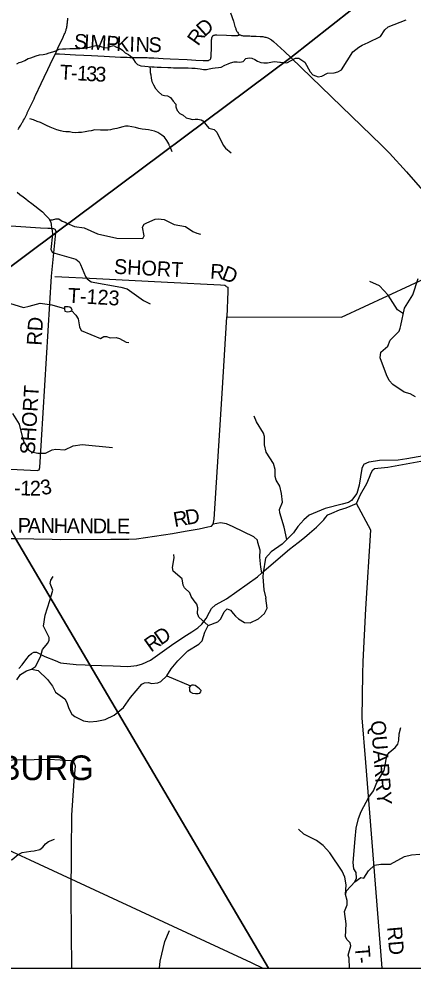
# Model space of a CAD drawing. Extents: x 0 to 1052, y -194 to 246.
# Drawn here: x 4.134 to 5.648, y 14.205 to 17.846 of the extents above; entities that cross this region are included whole.
import ezdxf

# ---------------------------------------------------------------- set-up
doc = ezdxf.new("R2010")
doc.units = 0
for name, color, linetype in [('GM_X_Corporation', 7, 'Continuous'), ('GM_X_Corporation_Text', 7, 'Continuous'), ('GM_X_County_Road', 7, 'Continuous'), ('GM_X_County_Road_Text', 7, 'Continuous'), ('GM_X_Minor_Lake', 7, 'Continuous'), ('GM_X_Minor_River', 7, 'Continuous'), ('GM_X_Rail_Line', 7, 'Continuous'), ('GM_X_State_Route', 7, 'Continuous'), ('GM_X_Township_Road', 7, 'Continuous'), ('GM_X_Township_Road_Text', 7, 'Continuous')]:
    doc.layers.add(name, color=color, linetype=linetype)

msp = doc.modelspace()

# ---------------------------------------------------------------- linework, layer by layer
at = {"layer": 'GM_X_Corporation'}
for points in [[(5.491, 17.9457), (5.1788, 17.6981), (4.2749, 17.0262), (3.6964, 16.595), (3.6869, 16.5875), (3.6921, 16.5787), (4.0068, 16.0455), (4.1203, 15.8533), (4.4065, 15.3682), (5.0927, 14.2055), (8.7822, 14.2055), (8.7822, 19.8853)], [(5.491, 17.9457), (5.1788, 17.6981), (4.2749, 17.0262), (3.6964, 16.595)], [(3.6964, 16.595), (4.2749, 17.0262), (5.1788, 17.6981), (5.491, 17.9457)], [(3.6964, 16.595), (4.2749, 17.0262), (5.1788, 17.6981), (5.491, 17.9457)], [(2.3779, 14.2055), (5.0927, 14.2055), (4.4065, 15.3682), (4.1203, 15.8533)], [(2.3779, 14.2055), (8.7822, 14.2055)]]:
    msp.add_lwpolyline(points, dxfattribs=at)
at = {"layer": 'GM_X_County_Road'}
for points in [[(3.8855, 17.0657), (3.8945, 17.0651), (3.9379, 17.0625), (4.0353, 17.0565), (4.0912, 17.053), (4.1216, 17.0513), (4.2171, 17.0454), (4.245, 17.0437), (4.2555, 17.0431), (4.2636, 17.0425), (4.2655, 17.0423), (4.2672, 17.0418), (4.2696, 17.0409), (4.2711, 17.04), (4.2725, 17.0387), (4.2735, 17.0372), (4.274, 17.0361), (4.2745, 17.0349), (4.2748, 17.0338), (4.2751, 17.0325), (4.2753, 17.0297), (4.2751, 17.0257)], [(4.2609, 15.8504), (4.2924, 15.8499), (4.4871, 15.8502), (4.5558, 15.8503), (4.5854, 15.8513), (4.7233, 15.8727), (4.7727, 15.8812), (4.8266, 15.8908), (4.86, 15.8975), (4.8741, 15.9005), (4.8794, 15.9077), (4.8841, 15.9278), (4.9141, 16.4089), (4.9327, 16.7033), (5.3736, 16.7026), (5.7266, 16.866), (5.9068, 16.9578)], [(4.4956, 15.3646), (4.5516, 15.3626), (4.5869, 15.3659), (4.609, 15.3717), (4.6386, 15.3858), (4.7289, 15.4498), (4.777, 15.4824), (4.7974, 15.4957), (4.8207, 15.5106), (4.8361, 15.5245), (4.8533, 15.546), (4.8654, 15.5704), (4.8737, 15.5842), (4.8892, 15.5986), (4.9058, 15.6074), (4.9312, 15.6218), (5.0502, 15.7058), (5.0667, 15.7219), (5.1733, 15.8119), (5.2071, 15.838), (5.2304, 15.8576), (5.2502, 15.8731), (5.2765, 15.8969), (5.3047, 15.9244), (5.3111, 15.9343), (5.3199, 15.9433), (5.3355, 15.9497), (5.3659, 15.9629), (5.3914, 15.9711), (5.4302, 15.988), (5.4458, 16.0213), (5.4701, 16.0647), (5.4802, 16.0883), (5.4871, 16.1045), (5.4931, 16.1165), (5.5, 16.1216), (5.5514, 16.1267), (5.6776, 16.1495)], [(3.4438, 15.9251), (3.5208, 15.8958), (3.6683, 15.8481), (3.7274, 15.8293), (3.7384, 15.8266), (4.0062, 15.8493), (4.054, 15.8506), (4.1026, 15.853), (4.1205, 15.8527), (4.2609, 15.8504)], [(4.1336, 15.3538), (4.1462, 15.3686), (4.1565, 15.3822), (4.1652, 15.3946), (4.1734, 15.4044), (4.182, 15.4126), (4.1911, 15.4172), (4.2013, 15.4167), (4.2328, 15.4004), (4.2726, 15.3848), (4.2931, 15.3762), (4.3533, 15.37), (4.3877, 15.3684), (4.4067, 15.3677), (4.4956, 15.3646)]]:
    msp.add_lwpolyline(points, dxfattribs=at)
at = {"layer": 'GM_X_Minor_Lake'}
for points in [[(4.3089, 16.7334), (4.3095, 16.7246), (4.3201, 16.7222), (4.3281, 16.7237), (4.3327, 16.7247), (4.3381, 16.7296), (4.3359, 16.7357), (4.3287, 16.7403), (4.3227, 16.7423), (4.3166, 16.7424), (4.3123, 16.7424)], [(4.3123, 16.7424), (4.3093, 16.7421), (4.3089, 16.7334)], [(4.7984, 15.2901), (4.7934, 15.2875), (4.788, 15.2819), (4.7888, 15.276), (4.7892, 15.2683), (4.7918, 15.2648), (4.8008, 15.2601), (4.8118, 15.2583), (4.8224, 15.2589), (4.8289, 15.2603), (4.8332, 15.2651), (4.8336, 15.2697), (4.8269, 15.2763), (4.821, 15.2817), (4.8161, 15.2856), (4.8105, 15.2887), (4.8044, 15.29)], [(4.8044, 15.29), (4.7984, 15.2901)]]:
    msp.add_lwpolyline(points, dxfattribs=at)
at = {"layer": 'GM_X_Minor_River'}
for points in [[(5.4749, 17.7558), (5.5233, 17.7791), (5.54, 17.805), (5.5523, 17.8162), (5.6217, 17.8428)], [(4.1254, 17.6736), (4.135, 17.6787), (4.1449, 17.682), (4.1567, 17.6868), (4.1697, 17.6939), (4.1793, 17.6968), (4.1896, 17.7008), (4.1999, 17.7045), (4.2132, 17.7089), (4.2265, 17.7102), (4.2402, 17.7123), (4.2505, 17.716), (4.2643, 17.7203), (4.275, 17.7244), (4.2887, 17.7299), (4.3009, 17.7316), (4.3142, 17.7318), (4.3298, 17.7324), (4.3419, 17.733), (4.3575, 17.7328), (4.3681, 17.733), (4.3845, 17.734), (4.4043, 17.7383), (4.4188, 17.7423), (4.4291, 17.7444), (4.4393, 17.7435), (4.4518, 17.7392), (4.4643, 17.7364), (4.4742, 17.7358), (4.4845, 17.7399), (4.4967, 17.7439), (4.5091, 17.7377), (4.5193, 17.7356), (4.5318, 17.7264), (4.5419, 17.7167), (4.5547, 17.7101), (4.5671, 17.7001), (4.5738, 17.6905), (4.5798, 17.6809), (4.5891, 17.671), (4.6027, 17.6658), (4.6171, 17.6645), (4.6297, 17.664), (4.6437, 17.6627), (4.6536, 17.6621), (4.6646, 17.6616), (4.6798, 17.6607), (4.706, 17.6603), (4.7174, 17.6594), (4.7272, 17.6589), (4.7379, 17.6584), (4.7492, 17.6583), (4.7606, 17.6589), (4.772, 17.6591), (4.7838, 17.6586), (4.7982, 17.658), (4.8108, 17.6575), (4.8202, 17.6562), (4.8297, 17.6546), (4.8426, 17.6521), (4.8548, 17.6519), (4.8643, 17.6549), (4.8776, 17.6577), (4.8875, 17.6591), (4.9004, 17.6601), (4.9107, 17.6615), (4.9249, 17.6685), (4.9371, 17.6744), (4.947, 17.6777), (4.9604, 17.6813), (4.9718, 17.6819), (4.982, 17.6803), (4.9957, 17.6824), (5.0054, 17.6948), (5.0187, 17.6969), (5.0282, 17.6953), (5.0406, 17.6909), (5.0504, 17.684), (5.0633, 17.6789), (5.0743, 17.6776), (5.0883, 17.6778), (5.1142, 17.6828), (5.1264, 17.6818)], [(5.1386, 17.6799), (5.1635, 17.6784), (5.1964, 17.6955), (5.2085, 17.6957), (5.2319, 17.6799), (5.2522, 17.6428), (5.2627, 17.6324), (5.2839, 17.6246), (5.2968, 17.6271), (5.3186, 17.6386), (5.3448, 17.6398), (5.3585, 17.6431), (5.3734, 17.6512), (5.4167, 17.7194), (5.439, 17.7377), (5.4524, 17.7459), (5.4749, 17.7558)], [(4.6366, 17.6633), (4.6375, 17.6517), (4.6385, 17.6411), (4.6399, 17.6312), (4.6416, 17.6186), (4.6445, 17.6068), (4.6508, 17.5939), (4.6585, 17.5793), (4.6698, 17.5667), (4.6829, 17.5555), (4.6927, 17.5519), (4.7049, 17.5506), (4.7158, 17.5444), (4.7263, 17.531), (4.7371, 17.5187), (4.737, 17.5088), (4.7417, 17.4955), (4.7518, 17.4836), (4.7647, 17.4766), (4.7763, 17.4666), (4.7869, 17.4638), (4.8009, 17.4602), (4.8108, 17.4612), (4.8207, 17.4618), (4.8343, 17.4597), (4.8397, 17.4551)], [(5.1264, 17.6818), (5.1358, 17.6806), (5.1386, 17.6799)], [(4.712, 17.3591), (4.71, 17.3668), (4.7018, 17.3798), (4.6929, 17.3921), (4.6827, 17.3998), (4.668, 17.4106), (4.6552, 17.4154), (4.6431, 17.4186), (4.631, 17.4202), (4.6203, 17.4215), (4.6074, 17.4228), (4.5938, 17.426), (4.5821, 17.4296), (4.5681, 17.4328), (4.5533, 17.4349), (4.543, 17.4347), (4.5331, 17.4325), (4.5194, 17.4285), (4.5095, 17.426), (4.495, 17.4228), (4.4855, 17.4206), (4.4748, 17.4196), (4.4612, 17.419), (4.4471, 17.42), (4.4258, 17.4202), (4.4114, 17.4174), (4.4007, 17.4153), (4.3882, 17.4135), (4.3741, 17.4107), (4.3623, 17.4104), (4.3513, 17.4098), (4.3384, 17.4111), (4.3274, 17.4128), (4.3145, 17.4137), (4.3038, 17.4146), (4.2936, 17.4166), (4.2792, 17.4202), (4.2671, 17.4257), (4.2539, 17.4316), (4.2403, 17.4378), (4.2166, 17.4484), (4.2037, 17.4524), (4.1897, 17.4594), (4.1757, 17.4633)], [(4.8397, 17.4551), (4.8633, 17.4275), (4.8837, 17.4215), (4.8946, 17.4119), (4.9186, 17.3619), (4.9272, 17.3504), (4.9493, 17.3331)], [(4.712, 17.3591), (4.7214, 17.3381)], [(4.1275, 17.1811), (4.1373, 17.1727), (4.15, 17.1634), (4.1598, 17.1564), (4.1696, 17.148), (4.1831, 17.1387), (4.2237, 17.1063), (4.2376, 17.0928), (4.2488, 17.0805), (4.2566, 17.0671), (4.258, 17.0572), (4.259, 17.0451), (4.2615, 17.0336), (4.2623, 17.0211)], [(4.2518, 17.0753), (4.2628, 17.0758), (4.2758, 17.0794), (4.2872, 17.08), (4.2996, 17.0703), (4.3109, 17.0668), (4.3181, 17.0631)], [(4.3181, 17.0631), (4.3475, 17.0501), (4.3842, 17.0455), (4.4351, 17.0217), (4.5093, 17.0057), (4.6102, 17.0041), (4.6148, 17.0139), (4.6088, 17.0473), (4.615, 17.059), (4.625, 17.0638), (4.657, 17.0775), (4.6688, 17.0792), (4.6919, 17.0771), (4.7303, 17.058), (4.7743, 17.0503), (4.8021, 17.0309), (4.8172, 17.0243), (4.8315, 17.02)], [(4.2623, 17.0211), (4.2568, 16.9617), (4.2631, 16.9498), (4.3519, 16.9252), (4.3647, 16.9141), (4.3703, 16.9045), (4.3894, 16.8588), (4.3965, 16.8492), (4.4115, 16.8372), (4.5254, 16.8173), (4.5496, 16.8105), (4.6121, 16.7665), (4.6381, 16.7537)], [(3.9964, 16.8212), (4.032, 16.7986), (4.0579, 16.7759), (4.0812, 16.7612), (4.1515, 16.7398), (4.1736, 16.7441), (4.2151, 16.7561), (4.2602, 16.7495), (4.309, 16.7357)], [(5.6109, 16.7156), (5.5878, 16.7301), (5.5527, 16.7864), (5.5195, 16.8219), (5.4822, 16.8384)], [(5.6572, 16.3968), (5.6366, 16.4077), (5.6143, 16.4149), (5.5704, 16.4441), (5.5559, 16.4595), (5.546, 16.4808), (5.5212, 16.5461), (5.5238, 16.568), (5.5511, 16.5908), (5.5598, 16.6145), (5.5945, 16.6489), (5.5985, 16.6594), (5.6013, 16.6708), (5.6156, 16.7373), (5.6468, 16.7884), (5.6671, 16.851)], [(4.3363, 16.728), (4.3526, 16.7101), (4.3615, 16.6963), (4.3664, 16.6651), (4.3727, 16.6514), (4.4474, 16.6205), (4.4604, 16.6276), (4.4703, 16.6278), (4.4843, 16.6231), (4.5074, 16.6236), (4.5203, 16.6208), (4.5455, 16.6061), (4.5565, 16.6044)], [(4.1088, 16.3321), (4.1348, 16.2919), (4.1489, 16.2337), (4.1533, 16.2208), (4.1707, 16.1936), (4.1816, 16.1855), (4.2062, 16.1811), (4.2165, 16.1805), (4.2355, 16.1811), (4.261, 16.1929), (4.2755, 16.1958), (4.3104, 16.1935), (4.3417, 16.2083), (4.377, 16.2131), (4.4929, 16.2019)], [(5.1628, 15.8496), (5.1526, 15.8964), (5.1362, 15.9513), (5.1349, 15.9649), (5.1462, 15.9921), (5.1429, 16.0263), (5.136, 16.0533), (5.1226, 16.077), (5.1187, 16.0907), (5.1186, 16.1177), (5.1117, 16.1405), (5.0834, 16.1845), (5.0773, 16.2119), (5.0766, 16.2449), (5.0734, 16.2575), (5.0458, 16.301), (5.0374, 16.3228)], [(5.4588, 16.1386), (5.4796, 16.1474), (5.5184, 16.1536), (5.5908, 16.1551), (5.6239, 16.1603), (5.6893, 16.171)], [(5.4588, 16.1386), (5.4514, 16.1216), (5.4411, 16.058), (5.4323, 16.0262), (5.4119, 15.9984), (5.3993, 15.9913), (5.376, 15.9852), (5.3098, 15.9678), (5.2484, 15.9431), (5.2277, 15.9251), (5.205, 15.8988), (5.188, 15.8751), (5.1446, 15.8313), (5.1024, 15.8014), (5.0805, 15.7782), (5.0715, 15.7217), (5.0709, 15.7062), (5.0744, 15.6561), (5.082, 15.6237)], [(4.8066, 15.6144), (4.7956, 15.631), (4.7909, 15.6443), (4.7699, 15.6639), (4.7647, 15.6735), (4.7612, 15.6978), (4.7263, 15.7274), (4.7238, 15.7419), (4.7307, 15.7786), (4.7283, 15.7923)], [(4.2519, 15.6148), (4.2637, 15.6549), (4.2534, 15.6808), (4.2566, 15.6937), (4.2655, 15.7072)], [(4.1253, 15.311), (4.1401, 15.332), (4.1627, 15.3459), (4.1826, 15.3516), (4.2083, 15.3462), (4.2437, 15.3118), (4.2629, 15.2867), (4.2742, 15.2637), (4.3105, 15.2376), (4.3182, 15.2246), (4.3243, 15.2047), (4.3305, 15.1913), (4.3371, 15.1798), (4.3479, 15.1705), (4.3813, 15.1539), (4.4067, 15.15), (4.4329, 15.1522), (4.4645, 15.1591), (4.4994, 15.1759), (4.5349, 15.2045), (4.5622, 15.2438), (4.6053, 15.2946), (4.6168, 15.2997), (4.6309, 15.3009), (4.6425, 15.2973), (4.6673, 15.2998), (4.6795, 15.3049), (4.7015, 15.3261), (4.7184, 15.3527), (4.7437, 15.3841), (4.782, 15.4228), (4.8253, 15.4478), (4.8373, 15.4601), (4.8475, 15.4944), (4.8613, 15.5196), (4.8976, 15.5337), (4.9088, 15.5456), (4.9222, 15.5719), (4.9335, 15.5831), (4.9467, 15.5783), (4.9563, 15.5656), (4.9656, 15.5555), (4.9771, 15.5447), (5.0004, 15.531), (5.0227, 15.529), (5.0542, 15.5455), (5.0769, 15.5656), (5.0868, 15.5859), (5.082, 15.6237)], [(4.1826, 15.3516), (4.1972, 15.362), (4.2165, 15.3992), (4.2239, 15.4275), (4.2445, 15.4514), (4.2493, 15.4631), (4.2495, 15.4733), (4.2287, 15.5173), (4.2341, 15.5594), (4.2519, 15.6148)], [(4.8613, 15.5196), (4.8243, 15.5518), (4.8197, 15.5656), (4.8212, 15.5875), (4.8166, 15.6009), (4.8066, 15.6144)], [(4.7015, 15.3261), (4.7934, 15.2875)], [(5.4489, 14.806), (5.4785, 14.8607), (5.4959, 14.8847), (5.5092, 14.9176), (5.537, 14.9631), (5.5476, 15.0198), (5.5557, 15.0322), (5.5797, 15.0516), (5.5897, 15.064), (5.5937, 15.0795), (5.594, 15.1038), (5.6012, 15.1284)], [(3.8011, 14.9727), (3.8224, 14.9571), (3.8286, 14.9463), (3.8556, 14.8494), (3.8948, 14.8202), (3.9117, 14.7907), (3.9413, 14.7487), (3.9551, 14.7405), (3.9917, 14.7273), (4.0025, 14.7172), (4.0188, 14.6767), (4.0359, 14.6403), (4.0606, 14.6212), (4.0824, 14.6121), (4.1084, 14.6218), (4.1304, 14.6411), (4.1461, 14.648), (4.18, 14.6542), (4.1921, 14.6551), (4.2135, 14.66), (4.2258, 14.6685), (4.2359, 14.6816), (4.2478, 14.6908), (4.2704, 14.6995)], [(5.424, 14.5365), (5.431, 14.5497), (5.4299, 14.5717), (5.4207, 14.5859), (5.4173, 14.6099), (5.4258, 14.7016), (5.4292, 14.7414), (5.4382, 14.7796), (5.4489, 14.806)], [(5.3886, 14.4878), (5.3907, 14.5242), (5.3856, 14.5543), (5.3754, 14.5765), (5.3277, 14.6476), (5.3024, 14.6754), (5.2766, 14.6952), (5.2288, 14.7192), (5.2079, 14.7385)], [(5.447, 14.5521), (5.4582, 14.5499), (5.4764, 14.5781), (5.5001, 14.6006), (5.5244, 14.6044), (5.5607, 14.604), (5.6148, 14.6336), (5.6425, 14.6401), (5.6739, 14.6419)], [(5.3886, 14.4878), (5.3926, 14.501), (5.424, 14.5365), (5.447, 14.5521)], [(5.4032, 14.2055), (5.4028, 14.2431), (5.3984, 14.2546), (5.4082, 14.2908), (5.4061, 14.3015), (5.3942, 14.3131), (5.3887, 14.3257), (5.3903, 14.375), (5.3847, 14.4218), (5.3947, 14.4478), (5.3946, 14.4645), (5.3886, 14.4878)], [(4.6738, 14.2055), (4.6763, 14.2322), (4.694, 14.307), (4.7122, 14.3496)]]:
    msp.add_lwpolyline(points, dxfattribs=at)
at = {"layer": 'GM_X_Rail_Line'}
msp.add_lwpolyline([(3.0187, 15.1565), (3.1162, 15.1123), (3.6083, 14.8817), (4.1755, 14.6202), (5.0257, 14.2265), (5.0707, 14.2055)], dxfattribs=at)
at = {"layer": 'GM_X_State_Route'}
for points in [[(4.1306, 17.4222), (4.134, 17.4272), (4.1364, 17.431), (4.1388, 17.4348), (4.1413, 17.4389), (4.1441, 17.4438), (4.1468, 17.4486), (4.1487, 17.4521), (4.1516, 17.4576), (4.1547, 17.4634), (4.1648, 17.4835), (4.1658, 17.4856), (4.1681, 17.4905), (4.192, 17.5403), (4.1934, 17.5433), (4.1952, 17.5471), (4.1977, 17.5524), (4.2196, 17.599), (4.2311, 17.6231), (4.2446, 17.6518), (4.2633, 17.6903), (4.2737, 17.7127), (4.2837, 17.7343), (4.304, 17.7769), (4.3081, 17.7861), (4.3098, 17.7899), (4.3111, 17.7932), (4.3121, 17.7957), (4.313, 17.798), (4.3139, 17.8007), (4.3147, 17.8032), (4.3153, 17.805), (4.3158, 17.8068), (4.3166, 17.81), (4.3174, 17.8134), (4.3181, 17.8169), (4.3187, 17.8206), (4.3192, 17.8246), (4.3196, 17.8273), (4.32, 17.8311), (4.3203, 17.8344), (4.3207, 17.8391), (4.321, 17.8424), (4.3212, 17.8447), (4.3215, 17.8491)], [(4.947, 17.8692), (4.9575, 17.8373), (4.9638, 17.8178), (4.9666, 17.8096), (4.9676, 17.8068), (4.9687, 17.8037), (4.97, 17.801), (4.9713, 17.7981), (4.9731, 17.795), (4.9756, 17.7916), (4.9777, 17.7894), (4.9804, 17.7871), (4.9833, 17.7855), (4.9862, 17.784), (4.9886, 17.7833), (4.9915, 17.7826), (4.9956, 17.782), (5.0018, 17.7816), (5.0065, 17.7814), (5.0115, 17.7812), (5.0161, 17.7811), (5.0209, 17.7809), (5.026, 17.7807), (5.0447, 17.7801), (5.0608, 17.779), (5.0655, 17.7786), (5.0702, 17.7782), (5.0743, 17.7775), (5.0788, 17.7768), (5.0823, 17.776), (5.0856, 17.7752), (5.0903, 17.7736), (5.095, 17.7715), (5.0972, 17.7702), (5.0993, 17.769), (5.1019, 17.7671), (5.1039, 17.7656), (5.1116, 17.7592), (5.1256, 17.7469), (5.1534, 17.7211), (5.179, 17.6975)], [(5.179, 17.6975), (5.4879, 17.3989), (5.5263, 17.3625), (5.5576, 17.3311), (5.6225, 17.26), (5.7363, 17.1292), (5.7582, 17.1047), (5.7902, 17.0703), (5.8502, 17.011), (5.8823, 16.9803), (5.9068, 16.9578)]]:
    msp.add_lwpolyline(points, dxfattribs=at)
at = {"layer": 'GM_X_Township_Road'}
for points in [[(4.2737, 17.7127), (4.2897, 17.712), (4.3517, 17.7089), (4.3833, 17.7072), (4.4125, 17.7057), (4.4615, 17.7034), (4.5235, 17.7001), (4.5382, 17.6995), (4.5496, 17.699), (4.5598, 17.6988), (4.5707, 17.6986), (4.5801, 17.6986), (4.6068, 17.6985), (4.6167, 17.6982), (4.626, 17.698), (4.6332, 17.6976), (4.6397, 17.6973), (4.6458, 17.697), (4.6521, 17.6966), (4.6874, 17.6949), (4.7147, 17.6935), (4.7799, 17.6901), (4.814, 17.6883), (4.8419, 17.6868), (4.8512, 17.6862), (4.8556, 17.6862), (4.8591, 17.6864), (4.8617, 17.6869), (4.8639, 17.6877), (4.8662, 17.6889), (4.8681, 17.6905), (4.8694, 17.6923), (4.8704, 17.6944), (4.8713, 17.6973), (4.8718, 17.7013), (4.8721, 17.7071), (4.8731, 17.7344), (4.874, 17.7667), (4.8742, 17.7688), (4.8744, 17.7711), (4.8747, 17.7733), (4.8752, 17.775), (4.8758, 17.7769), (4.8769, 17.7789), (4.8777, 17.7801), (4.8787, 17.7812), (4.8802, 17.7824), (4.8812, 17.783), (4.8826, 17.7836), (4.8851, 17.7843), (4.8881, 17.7847), (4.8936, 17.7847), (4.9309, 17.7835), (4.9505, 17.7826), (4.9538, 17.7824), (4.9569, 17.7824), (4.9617, 17.7824), (4.965, 17.7823), (4.9689, 17.7824), (4.9719, 17.7827), (4.9743, 17.7832), (4.9765, 17.7838), (4.9789, 17.7843), (4.9833, 17.7855)], [(4.0069, 16.0381), (4.007, 16.045), (4.0074, 16.0808), (4.0075, 16.1024), (4.0083, 16.1119), (4.0083, 16.118), (4.0095, 16.1202), (4.0122, 16.1225), (4.0235, 16.1232), (4.2038, 16.1141), (4.211, 16.1159), (4.2137, 16.1254), (4.2393, 16.5447), (4.2588, 16.8595), (4.2751, 17.0257)], [(4.2723, 16.8588), (4.4318, 16.8501), (4.7051, 16.836), (4.9081, 16.826), (4.9244, 16.8244), (4.9282, 16.8229), (4.9301, 16.8198), (4.9358, 16.8171), (4.9362, 16.8137), (4.9361, 16.8012), (4.9327, 16.7033)], [(5.4551, 15.3331), (5.4558, 15.3814), (5.4665, 15.5835), (5.4856, 15.8854), (5.4302, 15.988)], [(5.0667, 15.7219), (5.0633, 15.7434), (5.0595, 15.781), (5.06, 15.8087), (5.0515, 15.8375), (5.0504, 15.847), (5.0357, 15.8589), (4.9572, 15.898), (4.9318, 15.9091), (4.9083, 15.9138), (4.8794, 15.9077)], [(5.5298, 14.2055), (5.5281, 14.2215), (5.4663, 14.9936), (5.4527, 15.1657), (5.4551, 15.3331)], [(4.1925, 15.0044), (4.1096, 15.0031), (3.9964, 15.0008), (3.9402, 15.0057), (3.9257, 15.0053), (3.9091, 15.002), (3.8858, 14.9949), (3.8569, 14.9861), (3.855, 14.9861)], [(4.3369, 14.2055), (4.3347, 14.4811), (4.336, 14.6531), (4.3376, 14.7917), (4.3459, 14.9233), (4.3516, 14.9802), (4.3476, 14.9905), (4.3446, 14.9951), (4.3348, 15.0002), (4.2501, 15.0053), (4.1925, 15.0044)]]:
    msp.add_lwpolyline(points, dxfattribs=at)

# ---------------------------------------------------------------- texts
at = {"layer": 'GM_X_Corporation_Text'}
msp.add_text('LYNCHBURG', height=0.0947, rotation=0, dxfattribs=at).set_placement((3.6264, 14.9263))
at = {"layer": 'GM_X_County_Road_Text'}
for s, rotation, p in [('R', 9.8922, (4.7321, 15.8967)), ('D', 10.2002, (4.7784, 15.9048)), ('P', 359.5486, (4.129, 15.8754)), ('A', 359.5523, (4.1673, 15.8751)), ('N', 359.5523, (4.2173, 15.8747)), ('H', 359.5483, (4.2673, 15.8743)), ('A', 359.5523, (4.3173, 15.8739)), ('N', 359.5523, (4.3673, 15.8735)), ('D', 359.5483, (4.4173, 15.8731)), ('L', 359.563, (4.4673, 15.8727)), ('E', 359.849, (4.5102, 15.8724)), ('D', 35.0339, (4.6792, 15.4418)), ('R', 35.4147, (4.6413, 15.4148))]:
    msp.add_text(s, height=0.0568, rotation=rotation, dxfattribs=at).set_placement(p)
at = {"layer": 'GM_X_Township_Road_Text'}
for s, height, rotation, p in [('D', 0.0568, 42.3563, (4.847, 17.7754)), ('R', 0.0568, 54.7391, (4.8222, 17.7397)), ('S', 0.0568, 356.7817, (4.3444, 17.7326)), ('I', 0.0568, 356.7889, (4.3827, 17.7304)), ('M', 0.0568, 356.7848, (4.406, 17.7291)), ('P', 0.0568, 356.8103, (4.4676, 17.7256)), ('K', 0.0568, 357.4104, (4.5065, 17.7235)), ('I', 0.0568, 358.2395, (4.5574, 17.7212)), ('N', 0.0568, 358.7782, (4.5813, 17.7205)), ('S', 0.0568, 358.8595, (4.6313, 17.7194)), ('T', 0.0568, 356.8313, (4.2899, 17.6144)), ('1', 0.0568, 356.8457, (4.3557, 17.6108)), ('3', 0.0568, 356.8975, (4.3907, 17.6088)), ('3', 0.0568, 357.133, (4.4259, 17.6069)), ('-', 0.0568, 356.833, (4.3324, 17.6121)), ('SHORT', 0.05682, 357.0749, (4.4979, 16.8689)), ('R', 0.0568, 356.3874, (4.8671, 16.8505)), ('D', 0.0568, 339.17, (4.9093, 16.8485)), ('T-123', 0.05682, 356.6342, (4.3205, 16.7581)), ('RD', 0.05682, 86.5466, (4.2202, 16.5921)), ('SHORT', 0.05682, 86.4371, (4.1944, 16.1738)), ('1', 0.0568, 357.9377, (4.1383, 16.0189)), ('2', 0.0568, 0.3289, (4.1759, 16.0176)), ('3', 0.0568, 10.9944, (4.2223, 16.0189)), ('-', 0.0568, 357.1974, (4.1142, 16.02)), ('QUARRY', 0.05682, 274.5609, (5.485, 15.1532)), ('RD', 0.05682, 274.9272, (5.5481, 14.3625)), ('T', 0.0568, 274.5302, (5.4242, 14.2889)), ('-', 0.0568, 275.0706, (5.4276, 14.2459))]:
    msp.add_text(s, height=height, rotation=rotation, dxfattribs=at).set_placement(p)

doc.saveas('drawing.dxf')
